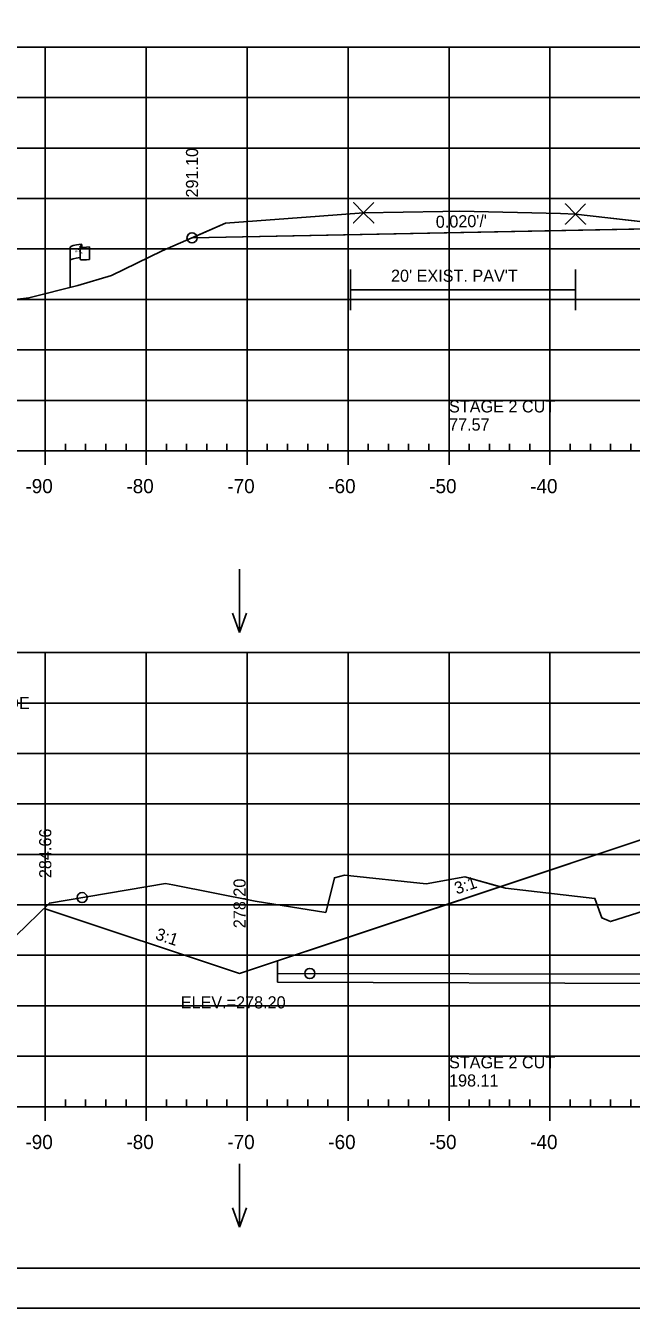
# Model space of a CAD drawing. Extents: x 1370843 to 1371177, y 380307 to 382654.
# Drawn here: x 1370921.8 to 1370981.8, y 381374.2 to 381501.3 of the extents above; entities that cross this region are included whole.
import ezdxf

# ---------------------------------------------------------------- set-up
doc = ezdxf.new("R2010")
doc.units = 0
for name, color, linetype in [('R_Axis', 7, 'Continuous'), ('R_Axis Annot', 7, 'Continuous'), ('R_Border', 7, 'Continuous'), ('R_Border Notes', 7, 'Continuous'), ('R_Exist Surface', 7, 'Continuous'), ('R_Exist Surface Annot', 7, 'Continuous'), ('R_Fin Surface', 7, 'Continuous'), ('R_Fin Surface Annot', 7, 'Continuous'), ('R_Grid', 7, 'Continuous'), ('R_No Plot', 7, 'Continuous'), ('R_ROW', 7, 'Continuous'), ('R_Water', 7, 'Continuous'), ('R_Water Annot', 7, 'Continuous')]:
    doc.layers.add(name, color=color, linetype=linetype)

msp = doc.modelspace()

# ---------------------------------------------------------------- linework, layer by layer
at = {"layer": 'R_Axis'}
for p, q in [((1370925.71, 381459.14), (1370925.71, 381459.84)), ((1370927.71, 381459.14), (1370927.71, 381459.84)), ((1370929.71, 381459.14), (1370929.71, 381459.84)), ((1370931.71, 381459.14), (1370931.71, 381459.84)), ((1370935.71, 381459.14), (1370935.71, 381459.84)), ((1370937.71, 381459.14), (1370937.71, 381459.84)), ((1370939.71, 381459.14), (1370939.71, 381459.84)), ((1370941.71, 381459.14), (1370941.71, 381459.84)), ((1370945.71, 381459.14), (1370945.71, 381459.84)), ((1370947.71, 381459.14), (1370947.71, 381459.84)), ((1370949.71, 381459.14), (1370949.71, 381459.84)), ((1370951.71, 381459.14), (1370951.71, 381459.84)), ((1370955.71, 381459.14), (1370955.71, 381459.84)), ((1370957.71, 381459.14), (1370957.71, 381459.84)), ((1370959.71, 381459.14), (1370959.71, 381459.84)), ((1370961.71, 381459.14), (1370961.71, 381459.84)), ((1370965.71, 381459.14), (1370965.71, 381459.84)), ((1370967.71, 381459.14), (1370967.71, 381459.84)), ((1370969.71, 381459.14), (1370969.71, 381459.84)), ((1370971.71, 381459.14), (1370971.71, 381459.84)), ((1370975.71, 381459.14), (1370975.71, 381459.84)), ((1370977.71, 381459.14), (1370977.71, 381459.84)), ((1370979.71, 381459.14), (1370979.71, 381459.84)), ((1370981.71, 381459.14), (1370981.71, 381459.84)), ((1370868.71, 381459.14), (1371158.71, 381459.14)), ((1370923.71, 381457.74), (1370923.71, 381459.14)), ((1370933.71, 381457.74), (1370933.71, 381459.14)), ((1370943.71, 381457.74), (1370943.71, 381459.14)), ((1370953.71, 381457.74), (1370953.71, 381459.14)), ((1370963.71, 381457.74), (1370963.71, 381459.14)), ((1370973.71, 381457.74), (1370973.71, 381459.14)), ((1370925.71, 381394.14), (1370925.71, 381394.84)), ((1370927.71, 381394.14), (1370927.71, 381394.84)), ((1370929.71, 381394.14), (1370929.71, 381394.84)), ((1370931.71, 381394.14), (1370931.71, 381394.84)), ((1370935.71, 381394.14), (1370935.71, 381394.84)), ((1370937.71, 381394.14), (1370937.71, 381394.84)), ((1370939.71, 381394.14), (1370939.71, 381394.84)), ((1370941.71, 381394.14), (1370941.71, 381394.84)), ((1370945.71, 381394.14), (1370945.71, 381394.84)), ((1370947.71, 381394.14), (1370947.71, 381394.84)), ((1370949.71, 381394.14), (1370949.71, 381394.84)), ((1370951.71, 381394.14), (1370951.71, 381394.84)), ((1370955.71, 381394.14), (1370955.71, 381394.84)), ((1370957.71, 381394.14), (1370957.71, 381394.84)), ((1370959.71, 381394.14), (1370959.71, 381394.84)), ((1370961.71, 381394.14), (1370961.71, 381394.84)), ((1370965.71, 381394.14), (1370965.71, 381394.84)), ((1370967.71, 381394.14), (1370967.71, 381394.84)), ((1370969.71, 381394.14), (1370969.71, 381394.84)), ((1370971.71, 381394.14), (1370971.71, 381394.84)), ((1370975.71, 381394.14), (1370975.71, 381394.84)), ((1370977.71, 381394.14), (1370977.71, 381394.84)), ((1370979.71, 381394.14), (1370979.71, 381394.84)), ((1370981.71, 381394.14), (1370981.71, 381394.84)), ((1370868.71, 381394.14), (1371158.71, 381394.14)), ((1370923.71, 381392.74), (1370923.71, 381394.14)), ((1370933.71, 381392.74), (1370933.71, 381394.14)), ((1370943.71, 381392.74), (1370943.71, 381394.14)), ((1370953.71, 381392.74), (1370953.71, 381394.14)), ((1370963.71, 381392.74), (1370963.71, 381394.14)), ((1370973.71, 381392.74), (1370973.71, 381394.14))]:
    msp.add_line(p, q, dxfattribs=at)
at = {"layer": 'R_Border'}
msp.add_line((1371171.89, 381378.14), (1370855.71, 381378.14), dxfattribs=at)
at = {"layer": 'R_Exist Surface'}
for points in [[(1370912.82, 381473.19), (1370922.1, 381474.29), (1370926.94, 381475.53), (1370930.26, 381476.52), (1370935.28, 381478.95), (1370941.56, 381481.69), (1370950.89, 381482.39), (1370955.25, 381482.73), (1370963.08, 381482.86), (1370964.78, 381482.89), (1370974.76, 381482.64), (1370976.24, 381482.6), (1370988.71, 381481.18), (1370989.43, 381481.09), (1370994.81, 381479.59), (1371007.85, 381475.97), (1371010.2, 381475.89), (1371049.05, 381474.7), (1371062.93, 381474.6)], [(1370920.78, 381411.07), (1370924.13, 381414.31), (1370935.61, 381416.25), (1370936.34, 381416.14), (1370944.49, 381414.52), (1370951.49, 381413.39), (1370951.76, 381414.42), (1370952.36, 381416.82), (1370953.37, 381417.09), (1370961.44, 381416.24), (1370965.29, 381416.93), (1370969.3, 381415.79), (1370978.17, 381414.78), (1370978.84, 381412.87), (1370979.69, 381412.48), (1370991.78, 381416.34)]]:
    msp.add_lwpolyline(points, dxfattribs=at)
at = {"layer": 'R_Exist Surface Annot'}
for p, q in [((1370953.95, 381473.09), (1370953.95, 381477.09)), ((1370976.24, 381473.09), (1370976.24, 381477.09)), ((1370953.95, 381475.09), (1370976.24, 381475.09))]:
    msp.add_line(p, q, dxfattribs=at)
at = {"layer": 'R_Fin Surface'}
for points in [[(1370938.25, 381480.24), (1370983.71, 381481.15), (1370993.71, 381481.35), (1370996.17, 381481.97), (1371000.71, 381483.1), (1371002.71, 381483.18), (1371013.71, 381483.4), (1371024.71, 381483.18), (1371026.71, 381483.1), (1371031.25, 381481.97), (1371042.71, 381479.1), (1371056.06, 381474.65)], [(1370923.59, 381413.79), (1370942.96, 381407.34), (1370982.71, 381420.59), (1370983.71, 381420.59), (1370990.11, 381421.35), (1371000.71, 381422.6), (1371002.71, 381422.68), (1371013.71, 381422.9), (1371024.71, 381422.68), (1371026.71, 381422.6), (1371036.65, 381421.36), (1371042.71, 381420.6), (1371043.21, 381420.43), (1371044.21, 381420.43), (1371084.1, 381407.14), (1371105.72, 381414.34)]]:
    msp.add_lwpolyline(points, dxfattribs=at)
at = {"layer": 'R_Grid'}
for p, q in [((1370868.71, 381499.14), (1371158.71, 381499.14)), ((1370923.71, 381459.14), (1370923.71, 381499.14)), ((1370933.71, 381459.14), (1370933.71, 381499.14)), ((1370943.71, 381459.14), (1370943.71, 381499.14)), ((1370953.71, 381459.14), (1370953.71, 381499.14)), ((1370963.71, 381459.14), (1370963.71, 381499.14)), ((1370973.71, 381459.14), (1370973.71, 381499.14)), ((1370868.71, 381494.14), (1371158.71, 381494.14)), ((1370868.71, 381489.14), (1371158.71, 381489.14)), ((1370868.71, 381484.14), (1371158.71, 381484.14)), ((1370868.71, 381479.14), (1371158.71, 381479.14)), ((1370868.71, 381474.14), (1371158.71, 381474.14)), ((1370868.71, 381469.14), (1371158.71, 381469.14)), ((1370868.71, 381464.14), (1371158.71, 381464.14)), ((1370868.71, 381459.14), (1371158.71, 381459.14)), ((1370868.71, 381439.14), (1371158.71, 381439.14)), ((1370923.71, 381394.14), (1370923.71, 381439.14)), ((1370933.71, 381394.14), (1370933.71, 381439.14)), ((1370943.71, 381394.14), (1370943.71, 381439.14)), ((1370953.71, 381394.14), (1370953.71, 381439.14)), ((1370963.71, 381394.14), (1370963.71, 381439.14)), ((1370973.71, 381394.14), (1370973.71, 381439.14)), ((1370868.71, 381434.14), (1371158.71, 381434.14)), ((1370868.71, 381429.14), (1371158.71, 381429.14)), ((1370868.71, 381424.14), (1371158.71, 381424.14)), ((1370868.71, 381419.14), (1371158.71, 381419.14)), ((1370868.71, 381414.14), (1371158.71, 381414.14)), ((1370868.71, 381409.14), (1371158.71, 381409.14)), ((1370868.71, 381404.14), (1371158.71, 381404.14)), ((1370868.71, 381399.14), (1371158.71, 381399.14)), ((1370868.71, 381394.14), (1371158.71, 381394.14))]:
    msp.add_line(p, q, dxfattribs=at)
at = {"layer": 'R_No Plot'}
msp.add_line((1370843.31, 381374.16), (1371176.64, 381374.16), dxfattribs=at)
for points in [[(1370843.3, 381587.49), (1371176.64, 381587.49), (1371176.64, 381374.16), (1370843.3, 381374.16)], [(1371089.63, 381583.6), (1371089.63, 381573.72), (1371125.36, 381573.72), (1371125.36, 381570.8), (1371148.56, 381570.8), (1371148.56, 381546.47), (1371171.89, 381546.47), (1371171.89, 381378.14), (1370855.71, 381378.14), (1370855.71, 381583.6)], [(1370938.25, 381480.24), (1370941.56, 381481.69), (1370950.89, 381482.39), (1370955.25, 381482.73), (1370963.08, 381482.86), (1370964.78, 381482.89), (1370974.76, 381482.64), (1370976.24, 381482.6), (1370988.19, 381481.24)], [(1370923.59, 381413.79), (1370924.13, 381414.31), (1370935.61, 381416.25), (1370936.34, 381416.14), (1370944.49, 381414.52), (1370951.49, 381413.39), (1370952.36, 381416.82), (1370953.37, 381417.09), (1370961.44, 381416.24), (1370965.29, 381416.93), (1370968.76, 381415.94), (1370942.96, 381407.34)]]:
    msp.add_lwpolyline(points, close=True, dxfattribs=at)
for points in [[(1370955.25, 381482.73), (1370954.25, 381483.73), (1370955.25, 381482.73), (1370954.25, 381481.73), (1370955.25, 381482.73), (1370956.25, 381481.73), (1370955.25, 381482.73), (1370956.25, 381483.73)], [(1370976.24, 381482.6), (1370975.24, 381483.6), (1370976.24, 381482.6), (1370975.24, 381481.6), (1370976.24, 381482.6), (1370977.24, 381481.6), (1370976.24, 381482.6), (1370977.24, 381483.6)], [(1370923.71, 381413.76), (1370942.96, 381407.34), (1370982.71, 381420.59), (1370983.71, 381420.59), (1371000.71, 381422.6), (1371013.71, 381422.9)], [(1370997.38, 381421.49), (1370990.11, 381421.35), (1370983.71, 381420.59), (1370982.71, 381420.59), (1370968.76, 381415.94), (1370969.3, 381415.79), (1370978.17, 381414.78), (1370978.84, 381412.87), (1370979.69, 381412.48), (1370991.78, 381416.34), (1370994.25, 381415.9)], [(1370982.71, 381420.59), (1370968.76, 381415.94), (1370969.3, 381415.79), (1370978.17, 381414.78), (1370978.84, 381412.87), (1370979.69, 381412.48), (1370991.78, 381416.34)]]:
    msp.add_lwpolyline(points, dxfattribs=at)
for centre in [(1370938.25, 381480.24), (1370927.36, 381414.86), (1370949.92, 381407.34)]:
    msp.add_circle(centre, 0.5, dxfattribs=at)
at = {"layer": 'R_ROW'}
for p, q in [((1370926.17, 381475.33), (1370926.17, 381479.28)), ((1370927.17, 381479.38), (1370927.17, 381479.36)), ((1370927.17, 381479.36), (1370927.17, 381478.14)), ((1370927.34, 381479.53), (1370927.34, 381479.29)), ((1370928.11, 381479.34), (1370928.11, 381478.1))]:
    msp.add_line(p, q, dxfattribs=at)
for centre, radius, start, end in [((1370927.25, 381479.38), 0.078, 88.6458, 274.2828), ((1370927.26, 381479.53), 0.0783, 263.0712, 93.9564), ((1370927.25, 381478.14), 0.0783, 180, 273.9564)]:
    msp.add_arc(centre, radius, start, end, dxfattribs=at)
for centre, major_axis, ratio, start_param, end_param in [((1370927.76, 381479.33), (-1.58, -0.04), 0.19887, 5.030368, 6.283185), ((1370928.46, 381479.44), (-1.23, -0.13), 0.052933, 0.159456, 1.268315), ((1370927.75, 381478.01), (-1.58, -0.04), 0.19887, 5.083035, 6.194897), ((1370928.46, 381478.2), (-1.23, -0.13), 0.052933, 0.159456, 1.268315)]:
    msp.add_ellipse(centre, major_axis=major_axis, ratio=ratio, start_param=start_param, end_param=end_param, dxfattribs=at)
at = {"layer": 'R_Water'}
for p, q in [((1370982.71, 381420.59), (1370946.72, 381408.59)), ((1370946.72, 381406.47), (1370946.72, 381408.59)), ((1370946.72, 381407.34), (1371080.66, 381407.14)), ((1370946.72, 381406.47), (1371080.66, 381406.04))]:
    msp.add_line(p, q, dxfattribs=at)
at = {"layer": 'R_Water Annot'}
for p, q in [((1370942.96, 381447.41), (1370942.96, 381441.12)), ((1370942.96, 381441.12), (1370942.26, 381443.04)), ((1370942.96, 381441.12), (1370943.66, 381443.04)), ((1370942.96, 381388.48), (1370942.96, 381382.2)), ((1370942.96, 381382.2), (1370942.26, 381384.12)), ((1370942.96, 381382.2), (1370943.66, 381384.12))]:
    msp.add_line(p, q, dxfattribs=at)

# ---------------------------------------------------------------- texts
at = {"layer": 'R_Axis Annot'}
for s, p in [('-90', (1370921.75, 381454.94)), ('-80', (1370931.75, 381454.94)), ('-70', (1370941.75, 381454.94)), ('-60', (1370951.75, 381454.94)), ('-50', (1370961.75, 381454.94)), ('-40', (1370971.75, 381454.94)), ('-90', (1370921.75, 381389.94)), ('-80', (1370931.75, 381389.94)), ('-70', (1370941.75, 381389.94)), ('-60', (1370951.75, 381389.94)), ('-50', (1370961.75, 381389.94)), ('-40', (1370971.75, 381389.94))]:
    msp.add_text(s, height=1.4, dxfattribs=at).set_placement(p)
at = {"layer": 'R_Border Notes'}
msp.add_text('284.66', height=1.2, rotation=90, dxfattribs=at).set_placement((1370924.31, 381416.79))
at = {"layer": 'R_Exist Surface Annot'}
msp.add_text("20' EXIST. PAV'T", height=1.2, dxfattribs=at).set_placement((1370957.96, 381475.89))
at = {"layer": 'R_Fin Surface Annot'}
for s, rotation, p in [('291.10', 90, (1370938.85, 381484.24)), ("0.020'/'", 1.1458, (1370962.41, 381481.23)), ('278.20', 90, (1370943.56, 381411.83)), ('3:1', 18.4349, (1370964.47, 381415.16)), ('3:1', 341.5651, (1370934.53, 381410.76))]:
    msp.add_text(s, height=1.2, rotation=rotation, dxfattribs=at).set_placement(p)
at = {"layer": 'R_No Plot'}
for s, p in [('STAGE 2 CUT', (1370963.71, 381462.94)), ('77.57', (1370963.71, 381461.14)), ('STAGE 2 CUT', (1370963.71, 381397.94)), ('198.11', (1370963.71, 381396.14))]:
    msp.add_text(s, height=1.2, dxfattribs=at).set_placement(p)
at = {"layer": 'R_ROW'}
for s, height, rotation, p in [('R ', 0.2, 9.9884, (1370926.69, 381478.78)), (' O', 0.2, 9.9884, (1370926.84, 381478.83)), ('W', 0.2, 351.1788, (1370927.17, 381478.66)), ('DWB 11-9-07', 0.001, 90, (1370927.34, 381479.29)), ('DWB 11-9-07', 0.001, 5.0717, (1370928.1, 381478.1)), ('DWB 11-9-07', 0.001, 90, (1370926.17, 381475.33))]:
    msp.add_text(s, height=height, rotation=rotation, dxfattribs=at).set_placement(p)
at = {"layer": 'R_Water Annot'}
for s, p in [('0.00% RT. DITCH GRADE', (1370903.1, 381433.54)), ('ELEV.=278.20', (1370937.13, 381403.88))]:
    msp.add_text(s, height=1.2, dxfattribs=at).set_placement(p)

doc.saveas('drawing.dxf')
